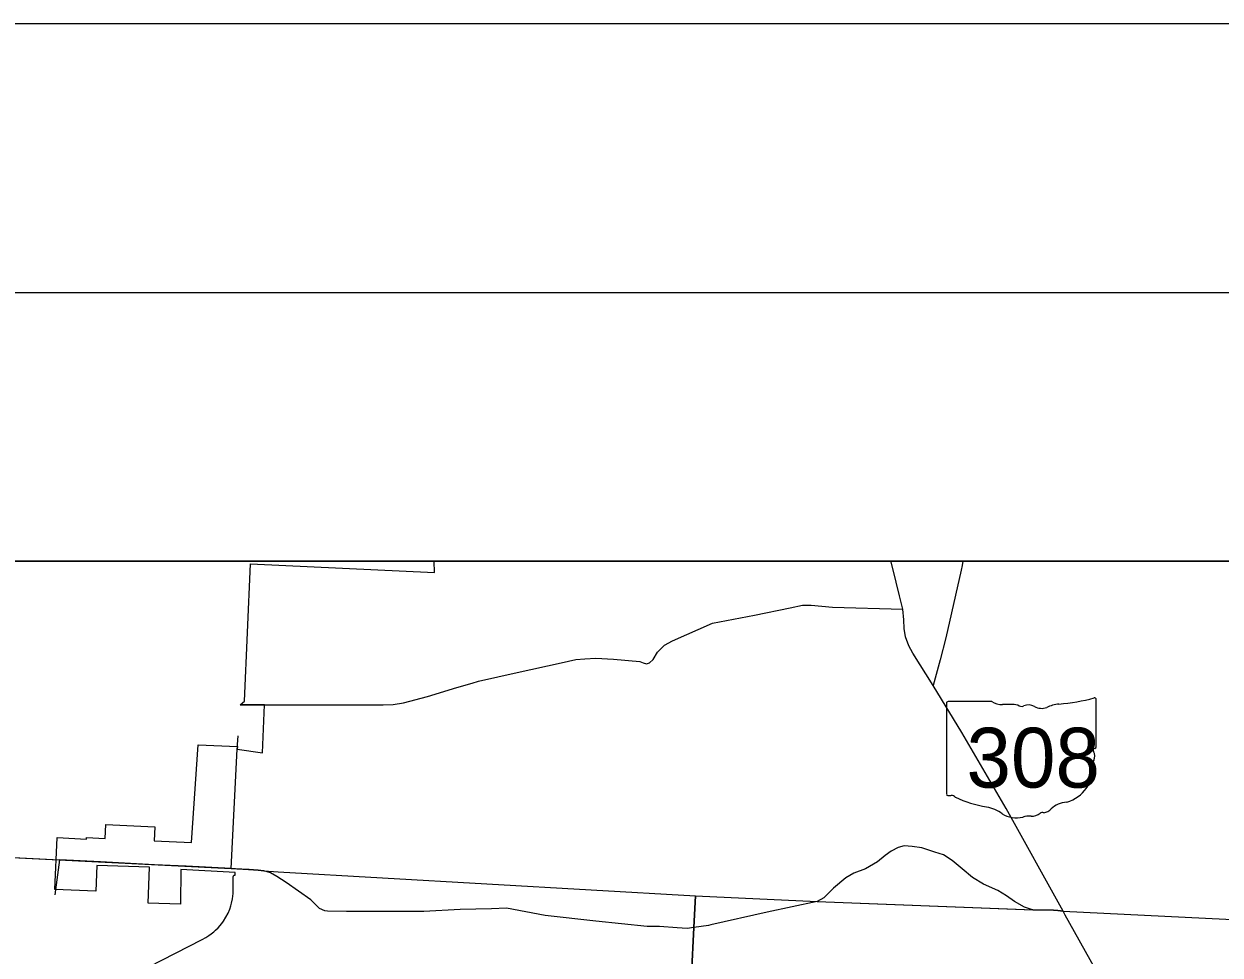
# Model space of a CAD drawing. Extents: x 41.3 to 81.6, y -19.3 to 2.7.
# Drawn here: x 44.697 to 46.925, y 1 to 2.734 of the extents above; entities that cross this region are included whole.
import ezdxf

# ---------------------------------------------------------------- set-up
doc = ezdxf.new("R2010")
doc.units = 0
for name, color, linetype in [('GM_X_Corporation', 7, 'Continuous'), ('GM_X_State_Route', 7, 'Continuous'), ('GM_X_State_Shield', 7, 'Continuous'), ('GM_X_Township', 7, 'Continuous'), ('GM_X_Township_Road', 7, 'Continuous'), ('SH_Border', 7, 'Continuous'), ('SH_Cut_Line', 7, 'Continuous'), ('SH_Data', 7, 'Continuous')]:
    doc.layers.add(name, color=color, linetype=linetype)

msp = doc.modelspace()

# ---------------------------------------------------------------- linework, layer by layer
at = {"layer": 'GM_X_Corporation'}
msp.add_lwpolyline([(44.9296, 0.9782), (45.0293, 1.0296), (45.0362, 1.0332), (45.0418, 1.0367), (45.0462, 1.0398), (45.0508, 1.0434), (45.0542, 1.0464), (45.0591, 1.0512), (45.0658, 1.0591), (45.069, 1.0635), (45.0735, 1.0706), (45.0775, 1.0784), (45.0807, 1.086), (45.0827, 1.0922), (45.0839, 1.0968), (45.0856, 1.1052), (45.0866, 1.1151), (45.0868, 1.1227), (45.0871, 1.1456), (45.087, 1.1459), (45.087, 1.1462), (45.0871, 1.1467), (45.0872, 1.1472), (45.0874, 1.1475), (45.0876, 1.1479), (45.0879, 1.1482), (45.0884, 1.1486), (45.0887, 1.1488), (45.089, 1.149), (45.0894, 1.1491), (45.0899, 1.1492), (45.0903, 1.1492), (45.0907, 1.1492), (45.0909, 1.154), (44.9894, 1.1598), (44.9886, 1.0953), (44.9285, 1.0971), (44.9309, 1.1637), (44.8329, 1.1673), (44.8311, 1.1193), (44.7551, 1.1222), (44.759, 1.2189), (44.8139, 1.2162), (44.814, 1.219), (44.8486, 1.2173), (44.8498, 1.2435), (44.9409, 1.2392), (44.9397, 1.2129), (45.009, 1.2096), (45.0217, 1.392), (45.0948, 1.3884), (45.0945, 1.3835), (45.1417, 1.3771), (45.1453, 1.4662), (45.0999, 1.4662), (45.1077, 1.4727), (45.119, 1.7284), (45.4619, 1.7124), (45.4613, 1.7338), (43.2645, 1.7338)], dxfattribs=at)
at = {"layer": 'GM_X_State_Route'}
msp.add_line((46.3119, 1.7326), (46.3116, 1.7338), dxfattribs=at)
for points in [[(46.6364, 1.0746), (46.6323, 1.082), (46.526, 1.2732), (46.4438, 1.4144), (46.3902, 1.5024), (46.3522, 1.5624), (46.3453, 1.5759), (46.3387, 1.5928), (46.3361, 1.6081), (46.3359, 1.6243), (46.3341, 1.6442), (46.3279, 1.6693), (46.3212, 1.6946), (46.3119, 1.7326)], [(46.7771, 0.8237), (46.7485, 0.8728), (46.7062, 0.9494), (46.6917, 0.9757), (46.6364, 1.0746)]]:
    msp.add_lwpolyline(points, dxfattribs=at)
at = {"layer": 'GM_X_State_Shield'}
for p, q in [((46.4996, 1.4721), (46.4181, 1.4721)), ((46.6938, 1.3879), (46.6938, 1.4763)), ((46.4153, 1.4692), (46.4153, 1.3002)), ((46.6937, 1.3879), (46.6938, 1.3879))]:
    msp.add_line(p, q, dxfattribs=at)
for centre, major_axis, start_param, end_param in [((46.4185, 1.4696), (0.00323, 0), 1.712693, 3.28349), ((46.519, 1.4918), (0.0313, 0), 4.042523, 4.731795), ((46.5946, 1.7026), (0.2953, 0), 4.814394, 5.042369), ((46.6907, 1.4767), (0.0031, 0), 6.141152, 7.989035), ((46.5294, 1.3772), (0.1123, 0), 1.404758, 1.657858), ((46.5549, 1.4705), (0.00903, 0), 3.836095, 5.185415), ((46.5681, 1.4509), (0.0188, 0), 0.950623, 2.079405), ((46.5924, 1.4777), (0.0226, 0), 4.081561, 5.145723), ((46.6322, 1.4205), (0.0594, 0), 1.699011, 2.107814), ((46.693, 1.3814), (0.0048, 0), 1.883978, 3.671073), ((46.6904, 1.3876), (0.00332, 0), 5.05454, 6.418171), ((46.7049, 1.3509), (0.021, 0), 2.387724, 3.262537), ((46.6625, 1.3702), (0.0288, 0), 5.934695, 6.695948), ((46.6111, 1.3396), (0.0739, 0), 5.101752, 6.440018), ((46.4185, 1.2998), (0.00325, 0), 3.00124, 4.508301), ((46.419, 1.3171), (0.0248, 0), 4.665946, 4.897461), ((46.4241, 1.2904), (0.00895, 0), 0.519207, 1.627899), ((46.5372, 1.4423), (0.2132, 0), 4.195997, 4.488961), ((46.4736, 1.2242), (0.0667, 0), 0.823519, 1.323587), ((46.591, 1.2838), (0.0239, 0), 4.937069, 5.64225), ((46.6423, 1.2527), (0.0404, 0), 1.647645, 2.488434), ((46.5458, 1.2896), (0.0423, 0), 4.026481, 4.996735), ((46.5702, 1.2311), (0.0348, 0), 1.495662, 1.94098), ((46.5733, 1.2769), (0.0226, 0), 4.691044, 5.507374), ((46.5937, 1.2605), (0.00635, 0), 1.147584, 2.315152)]:
    msp.add_ellipse(centre, major_axis=major_axis, ratio=0.8, start_param=start_param, end_param=end_param, dxfattribs=at)
at = {"layer": 'GM_X_Township'}
for points in [[(43.8231, 1.2245), (45.083, 1.1614), (45.1156, 1.1595), (45.1332, 1.1586), (45.1439, 1.1572), (45.1704, 1.1555), (45.9476, 1.1106), (46.1745, 1.1003), (46.5758, 1.0845), (46.6145, 1.084), (46.6225, 1.0834), (46.6323, 1.082), (46.9356, 1.0671), (47.0053, 1.0645), (47.1126, 1.0599), (47.341, 1.0494), (48.1003, 1.0179), (48.1087, 1.2045), (48.132, 1.668), (48.1343, 1.7338), (43.8015, 1.7338)], [(44.1816, 1.2065), (44.7642, 1.1774), (45.083, 1.1614), (45.1156, 1.1595), (45.1332, 1.1586), (45.1439, 1.1572), (45.1704, 1.1555), (45.9476, 1.1106), (45.9447, 1.0518), (45.9228, 0.6112), (45.9185, 0.5251), (45.8949, 0.0505), (45.8682, -0.4861), (45.8674, -0.4918), (45.8654, -0.5072), (45.8638, -0.5331), (45.8627, -0.5366), (45.8423, -1.0023), (46.3278, -1.0295), (46.8046, -1.0557), (46.892, -1.0615), (46.8967, -1.0581), (47.3982, -1.085)], [(47.3982, -1.085), (46.8967, -1.0581), (46.892, -1.0615), (46.8046, -1.0557), (46.3278, -1.0295), (45.8423, -1.0023), (45.8627, -0.5366), (45.8638, -0.5331), (45.8654, -0.5072), (45.8674, -0.4918), (45.8682, -0.4861), (45.8949, 0.0505), (45.9185, 0.5251), (45.9228, 0.6112), (45.9447, 1.0518), (45.9476, 1.1106), (46.1745, 1.1003), (46.5449, 1.0858), (46.5758, 1.0845), (46.6145, 1.084), (46.6225, 1.0834), (46.6323, 1.082), (46.9356, 1.0671)]]:
    msp.add_lwpolyline(points, dxfattribs=at)
at = {"layer": 'GM_X_Township_Road'}
msp.add_line((46.4459, 1.7338), (46.4443, 1.7255), dxfattribs=at)
for points in [[(46.4443, 1.7255), (46.4425, 1.7166), (46.414, 1.591), (46.4036, 1.5497), (46.3902, 1.5024)], [(45.1415, 1.4662), (45.1453, 1.4662), (45.1971, 1.4662), (45.3664, 1.4659), (45.385, 1.4668), (45.4042, 1.4699), (45.4488, 1.4815), (45.5036, 1.4982), (45.5319, 1.5067), (45.5437, 1.5101), (45.6155, 1.5261), (45.6976, 1.5445), (45.7252, 1.5504), (45.7418, 1.5519), (45.762, 1.5528), (45.795, 1.551), (45.8443, 1.5466), (45.8503, 1.5443), (45.8564, 1.5427), (45.8619, 1.5446), (45.8692, 1.5506), (45.8773, 1.564), (45.8831, 1.5707), (45.8899, 1.5774), (45.905, 1.585), (45.9797, 1.6185), (46.0576, 1.633), (46.124, 1.6469), (46.1471, 1.6515), (46.1634, 1.652), (46.2029, 1.6479), (46.3341, 1.6442)], [(45.0999, 1.4662), (45.1415, 1.4662)], [(45.095, 1.3921), (45.0961, 1.4086)], [(45.083, 1.1615), (45.0945, 1.3835), (45.0948, 1.3884), (45.095, 1.3921)], [(46.5735, 1.0853), (46.5606, 1.0893), (46.5417, 1.1), (46.5268, 1.1103), (46.5109, 1.1204), (46.484, 1.1324), (46.4633, 1.1447), (46.4445, 1.161), (46.4257, 1.1762), (46.4097, 1.1871), (46.3935, 1.1918), (46.3692, 1.1997), (46.3515, 1.2026), (46.3363, 1.2034), (46.325, 1.2005), (46.312, 1.1936), (46.3008, 1.1856), (46.287, 1.174), (46.2646, 1.161), (46.2426, 1.1529), (46.2279, 1.1443), (46.205, 1.1246), (46.1945, 1.1146)], [(44.7554, 1.1125), (44.7642, 1.1774)], [(44.8397, 1.1736), (44.7642, 1.1774)], [(44.9404, 1.1686), (44.8397, 1.1736)], [(44.9991, 1.1656), (44.9404, 1.1686)], [(45.0914, 1.161), (45.083, 1.1615), (44.9991, 1.1656)], [(45.1167, 1.1595), (45.1156, 1.1595), (45.0914, 1.161)], [(45.9762, 1.0563), (45.9717, 1.0553), (45.9447, 1.0518), (45.9325, 1.0498), (45.9135, 1.051), (45.8807, 1.0533), (45.8577, 1.0538), (45.7625, 1.0635), (45.6679, 1.074), (45.6318, 1.081), (45.5957, 1.0879), (45.5679, 1.0865), (45.5095, 1.0851), (45.4418, 1.0813), (45.4053, 1.0812), (45.3605, 1.0815), (45.298, 1.0815), (45.2628, 1.082), (45.2577, 1.0827), (45.2477, 1.0873), (45.2315, 1.1034), (45.1857, 1.1352), (45.1684, 1.1464), (45.1563, 1.1533), (45.1439, 1.1572), (45.1332, 1.1586), (45.1167, 1.1595)], [(46.1945, 1.1146), (46.1867, 1.107), (46.1745, 1.1003), (46.0815, 1.08), (45.9762, 1.0563)], [(46.6323, 1.082), (46.6225, 1.0834), (46.6145, 1.084), (46.5758, 1.0845), (46.5735, 1.0853)], [(46.6323, 1.082), (46.9356, 1.0671)]]:
    msp.add_lwpolyline(points, dxfattribs=at)
at = {"layer": 'SH_Border'}
msp.add_lwpolyline([(42.7645, 2.2338), (74.7645, 2.2338), (74.7645, -18.7662), (42.7645, -18.7662)], close=True, dxfattribs=at)
at = {"layer": 'SH_Cut_Line'}
msp.add_lwpolyline([(41.2645, -19.2662), (75.2645, -19.2662), (75.2645, 2.7338), (41.2645, 2.7338)], close=True, dxfattribs=at)
at = {"layer": 'SH_Data'}
msp.add_line((43.2645, 1.7338), (50.2645, 1.7338), dxfattribs=at)

# ---------------------------------------------------------------- texts
at = {"layer": 'GM_X_State_Shield'}
msp.add_text('308', height=0.11138, dxfattribs=at).set_placement((46.4524, 1.3121))

doc.saveas('drawing.dxf')
